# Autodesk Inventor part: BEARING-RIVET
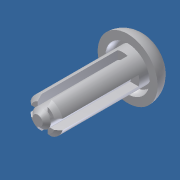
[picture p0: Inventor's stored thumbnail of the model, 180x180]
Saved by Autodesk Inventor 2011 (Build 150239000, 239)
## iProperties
Created: 2007-12
Part Number: BEARING-RIVET
Document SubType Name: Modeling
Density: 1 g/cm^3
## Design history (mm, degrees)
feature "Base1"
workplane "Work Plane1"
workplane "Work Plane2"
workplane "Work Plane3"
  workaxis "Work Axis1"
body "Solid1"
other parameters: "d0" = 0, "d1" = 0
